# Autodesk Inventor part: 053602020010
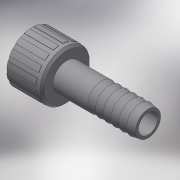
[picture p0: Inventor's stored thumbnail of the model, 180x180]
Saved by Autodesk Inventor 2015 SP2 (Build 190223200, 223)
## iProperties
Created: 2017-10
Part Number: 053602020010
Material: Generic
Description: PLASSON HOSE NOZZLE+NUT/THR. 1"-20
Document SubType Name: Modeling
Designer: KIM
Density: 1 g/cm^3
Appearance: Default
Author: KIM
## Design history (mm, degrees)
derived "053602.ipt"
feature "Solid1::053602.ipt"
tag "TaggingFeature1"
body "Solid1"
other parameters: "d0" = 72, "d1" = 170 deg, "d5" = 36.3492, "d6" = 14, "d8" = 28.8, "d9" = 30.291, "d10" = 21.6, "d11" = 12.96, "d12" = 18, "d13" = 35.74338, "d14" = 1.51455, "d17" = 3.0291, "d18" = 1.51455, "d19" = 20.16, "d20" = 0, "d22" = 360 deg, "d_" = 16, "H_" = 72, "G_" = 30.291
